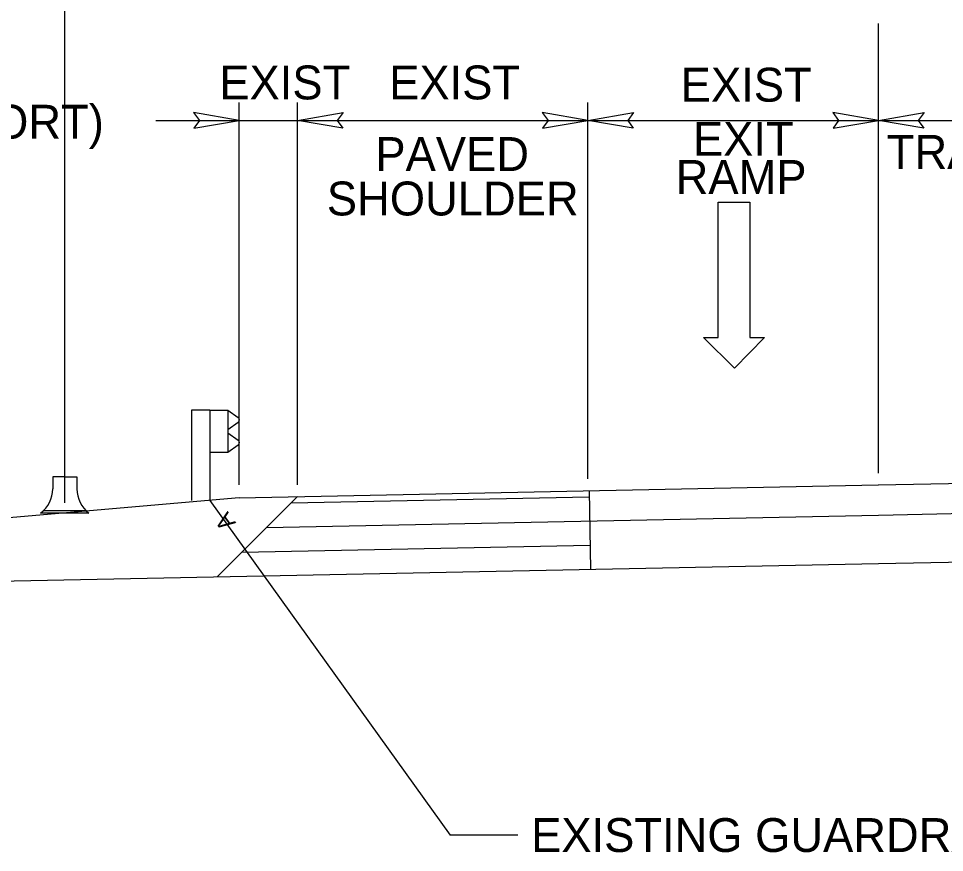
# Model space of a CAD drawing. Extents: x 1726582 to 1728895, y 538986 to 541550.
# Drawn here: x 1727049.1 to 1727240.4, y 539541.5 to 539713.9 of the extents above; entities that cross this region are included whole.
import ezdxf

# ---------------------------------------------------------------- set-up
doc = ezdxf.new("R2010")
doc.units = 0
for name, color, linetype in [('Default', 7, 'Continuous'), ('GSProposed', 7, 'Continuous'), ('GSReplace', 7, 'Continuous')]:
    doc.layers.add(name, color=color, linetype=linetype)

msp = doc.modelspace()

# ---------------------------------------------------------------- linework, layer by layer
at = {"layer": 'Default'}
for p, q in [((1727058.65, 539613.75), (1727058.65, 539767.66)), ((1727226.79, 539619.92), (1727226.79, 539712.82)), ((1727094.68, 539617.51), (1727094.68, 539696.51)), ((1727106.69, 539617.51), (1727106.69, 539696.51)), ((1727166.74, 539618.72), (1727166.74, 539696.51)), ((1727226.79, 539619.92), (1727226.79, 539696.51)), ((1727106.69, 539617.51), (1727106.69, 539695.3)), ((1727077.42, 539692.81), (1727106.8, 539692.81)), ((1727106.8, 539692.81), (1727166.85, 539692.81)), ((1727166.85, 539692.81), (1727226.89, 539692.81)), ((1727226.89, 539692.81), (1727286.94, 539692.81)), ((1727193.63, 539647.91), (1727193.63, 539675.91)), ((1727193.63, 539675.91), (1727200.23, 539675.91)), ((1727200.23, 539675.91), (1727200.23, 539647.91)), ((1727197.03, 539641.61), (1727190.63, 539647.91)), ((1727190.63, 539647.91), (1727193.63, 539647.91)), ((1727203.23, 539647.91), (1727197.03, 539641.61)), ((1727200.23, 539647.91), (1727203.23, 539647.91)), ((1727058.62, 539619.14), (1727056.12, 539619.14)), ((1727056.12, 539619.14), (1727056.12, 539616.64)), ((1727058.62, 539619.14), (1727061.12, 539619.14)), ((1727061.12, 539619.14), (1727061.12, 539616.64)), ((1727088.57, 539614.27), (1727138.27, 539545.08)), ((1727063.62, 539611.64), (1727053.62, 539611.64)), ((1727063.03, 539612.14), (1727054.2, 539612.14)), ((1727152.27, 539545.08), (1727138.27, 539545.08))]:
    msp.add_line(p, q, dxfattribs=at)
for points in [[(1727085.3, 539691.19), (1727094.68, 539692.81), (1727085.25, 539694.47), (1727086.45, 539692.81)], [(1727116.07, 539691.19), (1727106.69, 539692.81), (1727116.12, 539694.47), (1727114.92, 539692.81)], [(1727157.36, 539691.19), (1727166.74, 539692.81), (1727157.31, 539694.47), (1727158.51, 539692.81)], [(1727176.12, 539691.19), (1727166.74, 539692.81), (1727176.17, 539694.47), (1727174.97, 539692.81)], [(1727217.41, 539691.19), (1727226.79, 539692.81), (1727217.36, 539694.47), (1727218.55, 539692.81)], [(1727236.16, 539691.19), (1727226.79, 539692.81), (1727236.22, 539694.47), (1727235.02, 539692.81)]]:
    msp.add_lwpolyline(points, close=True, dxfattribs=at)
for centre, start, end in [((1727049.87, 539616.64), 306.8699, 0), ((1727067.37, 539616.64), 180, 233.1301)]:
    msp.add_arc(centre, 6.25, start, end, dxfattribs=at)
at = {"layer": 'GSReplace'}
for p, q in [((1727088.57, 539632.93), (1727084.84, 539632.93)), ((1727084.84, 539632.93), (1727084.84, 539614.27)), ((1727088.57, 539632.93), (1727088.57, 539614.27)), ((1727088.57, 539632.93), (1727092.3, 539632.93)), ((1727092.3, 539632.93), (1727092.3, 539624.22)), ((1727092.3, 539632.93), (1727094.48, 539631.4)), ((1727092.3, 539628.92), (1727094.48, 539630.45)), ((1727092.3, 539628.22), (1727094.48, 539626.7)), ((1727092.3, 539624.22), (1727094.48, 539625.74)), ((1727088.57, 539624.22), (1727092.3, 539624.22)), ((1727226.79, 539617.45), (1727461.04, 539622.13)), ((1727094.68, 539614.8), (1727226.76, 539617.45)), ((1727166.98, 539616.25), (1727167.31, 539600)), ((1727226.79, 539611.2), (1727461.04, 539617.02)), ((1727094.68, 539614.8), (1726880.23, 539596.02)), ((1727106.69, 539615.04), (1727090.1, 539598.46)), ((1727105.41, 539613.77), (1727167.01, 539615)), ((1727100.31, 539608.67), (1727226.79, 539611.2)), ((1727226.79, 539601.19), (1727461.04, 539605.87)), ((1727095.21, 539603.56), (1727167.21, 539605)), ((1726885.16, 539594.36), (1727226.79, 539601.19))]:
    msp.add_line(p, q, dxfattribs=at)
for centre, start, end in [((1727094.14, 539630.92), 304.9888, 54.997), ((1727094.14, 539626.22), 304.9634, 54.9941)]:
    msp.add_arc(centre, 0.583, start, end, dxfattribs=at)

# ---------------------------------------------------------------- texts
at = {"layer": 'Default'}
msp.add_text('A', height=3.5, rotation=125.6878, dxfattribs=at).set_placement((1727094.08, 539609.6))
msp.add_text('EXISTING GUARDRAIL', height=7, dxfattribs=at).set_placement((1727155.01, 539541.58))
at = {"layer": 'GSProposed'}
for s, height, p in [('EXIST', 7.005, (1727090.55, 539697.16)), ('EXIST', 7.005, (1727125.66, 539697.16)), ('EXIST', 7.005, (1727185.93, 539696.69)), ('EXIST (SUPPORT)', 7.0055, (1726985.5, 539689.04)), ('EXIT', 7.005, (1727188.44, 539685.5)), ('TRAVEL LANE', 7.0055, (1727228.52, 539682.8)), ('PAVED', 7.005, (1727122.81, 539682.36)), ('RAMP', 7.005, (1727184.87, 539677.62)), ('SHOULDER', 7.005, (1727112.78, 539673.17))]:
    msp.add_text(s, height=height, dxfattribs=at).set_placement(p)

doc.saveas('drawing.dxf')
